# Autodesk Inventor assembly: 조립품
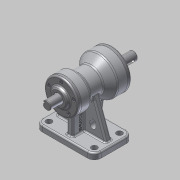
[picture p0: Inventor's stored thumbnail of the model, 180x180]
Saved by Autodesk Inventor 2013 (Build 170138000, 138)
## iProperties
Created: 2015-08
Part Number: 조립품
Document SubType Name: Assembly
Designer: ST1
Author: ST1
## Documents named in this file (10)
- C:\Users\ST1\Desktop\450805V1032\조립품.iam
- C:\Users\ST1\Desktop\450805V1032\본체.ipt
- C:\Users\ST1\Desktop\450805V1032\공용부품\M4x0.5.ipt
- C:\Users\ST1\Desktop\450805V1032\공용부품\뒤커버.ipt
- C:\Users\ST1\Desktop\450805V1032\공용부품\베어링 6203.ipt
- C:\Users\ST1\Desktop\450805V1032\공용부품\베어링 6205.ipt
- C:\Users\ST1\Desktop\450805V1032\공용부품\앞커버.ipt
- C:\Users\ST1\Desktop\450805V1032\공용부품\오일실 .ipt
- 오일실 .ipt
- C:\Users\ST1\Desktop\450805V1032\공용부품\축.ipt
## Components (10 placed, 1 different names)
1. M4x0.5:1
2. M4x0.5:2
3. M4x0.5:3
4. M4x0.5:5
5. M4x0.5:6
6. M4x0.5:7
7. M4x0.5:8
8. M4x0.5:9
9. M4x0.5:11
10. M4x0.5:12
